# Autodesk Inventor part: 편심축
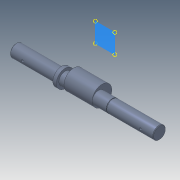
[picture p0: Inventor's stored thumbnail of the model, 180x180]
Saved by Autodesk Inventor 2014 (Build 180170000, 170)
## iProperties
Manager: 한국ATC센터
Company: 한국ATC센터
Created: 2014-10
Part Number: 편심축
Document SubType Name: Modeling
Designer: 한국ATC센터
Density: 7.86 g/cm^3
Material: 강, 연강
Mass: 1420.77 g
Surface Area: 286.546 cm^2
Volume: 180.759 cm^3
Appearance: 강철
Author: KYOUNG IL JANG
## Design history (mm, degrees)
sketch "스케치1"
  geometry: L1 (-142, 0)-(142, 0); L2 (-142, 0)-(-142, 12.5); L3 (-142, 12.5)-(-52, 12.5); L4 (-52, 12.5)-(-52, 17.5); L5 (-52, 17.5)-(-45, 17.5); L6 (-45, 17.5)-(-45, 12.5); L7 (-45, 12.5)-(48.65, 12.5); L8 (48.65, 12.5)-(48.65, 11.95); L9 (48.65, 11.95)-(50, 11.95); L10 (50, 11.95)-(50, 12.5); L11 (50, 12.5)-(142, 12.5); L12 (142, 12.5)-(142, 0); L13 (109, 12.5)-(109, 9.1); L14 (109, 9.1)-(134, 9.1); L15 (134, 9.1)-(134, 12.5); L16 (117, -12.5)-(119.5, -12.5); L17 (119.5, -12.5)-(117, -10); L18 (117, -10)-(117, -12.5); L19 (-109, 12.5)-(-109, 9.1); L20 (-109, 9.1)-(-134, 9.1); L21 (-134, 9.1)-(-134, 12.5); L22 (-117, -12.5)-(-117, -10); L23 (-117, -10)-(-114.5, -12.5); L24 (-114.5, -12.5)-(-117, -12.5); 2 further points
  constraints: 48 end point, 11 parallel, 8 perpendicular, 5 collinear, 4 point on line, 1 coincident, 1 horizontal, 1 midpoint, 1 vertical
  dimensions: "d0" = 284 distance of L1.start L1.end (derived); "d1" = 25 diameter of L3 L1; "d2" = 35 diameter of L5 L1; "d3" = 90 distance of L2.end L3.end; "d4" = 187 distance between parallel lines of L12 L6; "d6" = 1.35 distance of L8.end L9.end; "d7" = 23.9 diameter of L9 L1; "d8" = 3.4 distance between parallel lines of L14 L11; "d9" = 8 distance between parallel lines of L15 L12; "d10" = 25 distance of L13.end L14.end; "d11" = 25 diameter of L16 L1 (= d1); "d12" = 25 distance from line of L12 L16.start; "d13" = 45 deg angle of L17 L18; "d14" = 5 diameter of L16.end L18; "d27" = 92 distance between parallel lines of L10 L12; "d32" = 7 distance of L4.end L5.end; "d33" = 8 distance between parallel lines of L2 L21; "d34" = 25 distance between parallel lines of L21 L19; "d35" = 3.4 distance between parallel lines of L3 L20; "d36" = 25 distance from line of L22.start L2; "d37" = 5 diameter of L23.end L22
revolve "회전1" stored, may be unused: angle "d15" = 90 deg
revolve "회전2" stored, may be unused: angle "d16" = 90 deg
revolve "회전3" stored, may be unused: angle "d38" = 90 deg
extrude "돌출1" cut sketch "스케치1" stored distance "d17" = 8; taper "d18" = 0 deg
fillet "모깎기1" dims "d19" = 4
node "작업 평면1"
sketch "스케치2"
  geometry: C1 r 12.5 at (0, 0) reference; C2 r 19.5 at (0, 7); 1 further point
  constraints: 1 centre point, 1 tangent, 1 vertical alignment
  dimensions: "d21" = 7 distance of point (0, 0) C2.centre; "d30" = 39 diameter of C2 (derived)
extrude "돌출2" join sketch "스케치2" distance "d22" = 56; taper "d23" = 0 deg
chamfer "모따기1" distance "d24" = 1; stored, may be unused: second distance "d25" = 2, angle "d26" = 45 deg
node "솔리드1"
other parameters: "d20" = 16
